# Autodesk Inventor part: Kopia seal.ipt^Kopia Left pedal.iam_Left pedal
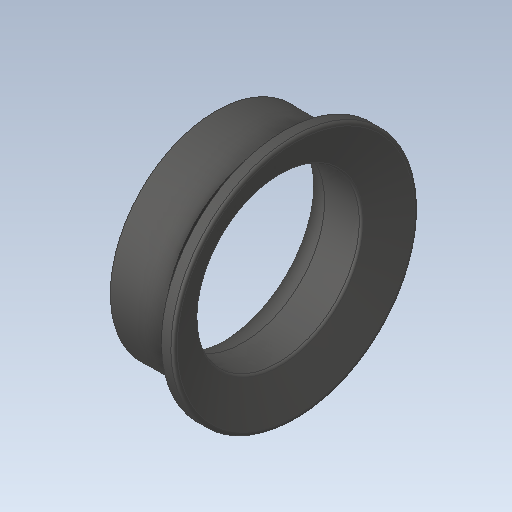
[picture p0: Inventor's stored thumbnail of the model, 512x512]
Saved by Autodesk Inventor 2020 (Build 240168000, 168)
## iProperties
Created: 2017-10
Part Number: Kopia seal.ipt^Kopia Left pedal.iam_Left pedal
Material: solidworks materials|POLIURETAN (11671)|229
Document SubType Name: Modeling
Designer: Tomasz
Density: 1.2252 g/cm^3
Appearance: 76,76,76
Sending System: SolidWorks 2017
Last Author: Tomasz
Last Saved: 2017-11-19
Author: Tomasz
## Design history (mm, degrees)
feature "seal.ipt"
node "Bryła1"
